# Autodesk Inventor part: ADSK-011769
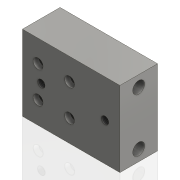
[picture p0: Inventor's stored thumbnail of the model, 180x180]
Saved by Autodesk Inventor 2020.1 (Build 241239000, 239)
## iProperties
Created: 2000-01
Part Number: ADSK-011769
Material: Aluminum
Document SubType Name: Modeling
Designer: sspink
Density: 2.71 g/cm^3
Appearance: Steel
Mass: 691.432 g
Surface Area: 392.008 cm^2
Volume: 255.141 cm^3
Control State: 0
Checked Out: False
Master: False
Shininess: 0.0
Length Units: 11269
Angle Units: 11279
Time Units: 11290
Mass Units: 11283
Length Display Precision: 3
Angle Display Precision: 2
Compacted: True
Dimensions: 98,4x76,2x38 mm
Mass: 0,691 kg
Density: 0.0
Volumn: 0.0
Area: 0.0
PropertySet Name: Model Information
Author: sspink
Revision Number: -
Title: ADSK-011769
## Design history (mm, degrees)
node "Extrusion1" dims "d2" = 37.973, "d3" = 0
node "Hole1" dims "d7" = 12.065, "d8" = 9.525, "d9" = 6.35, "d10" = 60 deg, "d11" = 19.05, "d12" = 118 deg
node "Hole2" dims "d17" = 5.5, "d18" = 10, "d19" = 5.7, "d20" = 60 deg, "d21" = 19.05, "d22" = 118 deg, "d31" = 6
node "Hole3" dims "d25" = 7.64684, "d26" = 9.525, "d27" = 5.461, "d28" = 60 deg, "d29" = 24.2, "d30" = 118 deg, "d32" = 18
node "Solide1"
node "Corps solides"
node "Corps surfaciques"
sketch "Sketch1"
  geometry: L1 (0, 0)-(98.425, 0) reference; L2 (98.425, 0)-(98.425, 76.2); L3 (98.425, 76.2)-(0, 76.2); L4 (0, 76.2)-(0, 0) reference
  constraints: 8 end point, 2 horizontal, 2 parallel, 1 perpendicular, 1 vertical
  dimensions: "d0" = 76.2 distance of L3.end L1.start; "d1" = 98.425 distance of L1.start L1.end
sketch "Sketch2"
  geometry: L1 (37.973, 0)-(37.973, 76.2) reference; L2 (0, 76.2)-(0, 0) reference; L3 (0, 38.1)-(37.973, 38.1); 2 further points
  constraints: 2 end point, 2 midpoint, 1 vertical alignment
  dimensions: "d4" = 19.05 distance from line of point (19.05, 65.1) L2; "d5" = 54.0004 distance of point (19.05, 11.1) point (19.05, 65.1); "d6" = 27.0002 distance from line of point (19.05, 11.1) L3 (= 0.5 x d5)
sketch "Sketch3"
  geometry: L1 (0, 0)-(0, 76.2) reference; L2 (98.425, 76.2)-(98.425, 0) reference; L3 (0, 38.1)-(98.425, 38.1); 4 further points
  constraints: 2 end point, 2 horizontal alignment, 2 midpoint, 2 vertical alignment
  dimensions: "d13" = 31.75 distance of point (15.875, 22.225) point (15.875, 53.975); "d14" = 15.875 distance from line of point (15.875, 53.975) L3 (= 0.5 x d13); "d15" = 15.875 distance from line of point (15.875, 53.975) L1; "d16" = 31.75 distance of point (47.625, 53.975) point (15.875, 53.975) (= d13)
sketch "Sketch4"
  geometry: L1 (0, 0)-(0, 76.2) reference; L2 (98.425, 76.2)-(98.425, 0) reference; L3 (0, 38.1)-(98.425, 38.1); 2 further points
  constraints: 2 end point, 2 midpoint, 2 point on line
  dimensions: "d23" = 19.05 distance from line of point (19.05, 38.1) L1; "d24" = 15.0876 distance from line of L2 point (83.337, 38.1)
